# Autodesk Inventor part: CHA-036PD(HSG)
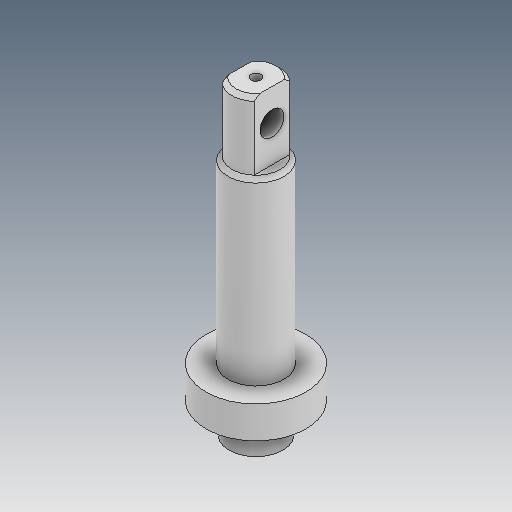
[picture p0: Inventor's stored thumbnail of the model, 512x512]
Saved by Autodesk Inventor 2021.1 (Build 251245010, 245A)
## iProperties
Created: 2021-05
Part Number: CHA-036PD(HSG)
Material: Ogólny
Document SubType Name: Modeling
Designer: user
Density: 1 g/cm^3
Appearance: Domyślna
Author: user
Revision Number: ÈÎºÎ
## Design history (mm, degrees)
feature "M3 ÂÝÎÆ¿×1"
node "Bryła1"
